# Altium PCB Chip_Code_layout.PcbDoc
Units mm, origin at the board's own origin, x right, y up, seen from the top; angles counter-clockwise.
Board outline 144.14 x 67.06 mm, 2 copper layers (Top Layer, Bottom Layer); 26 components, 21 nets, 115 pads, 10 vias.
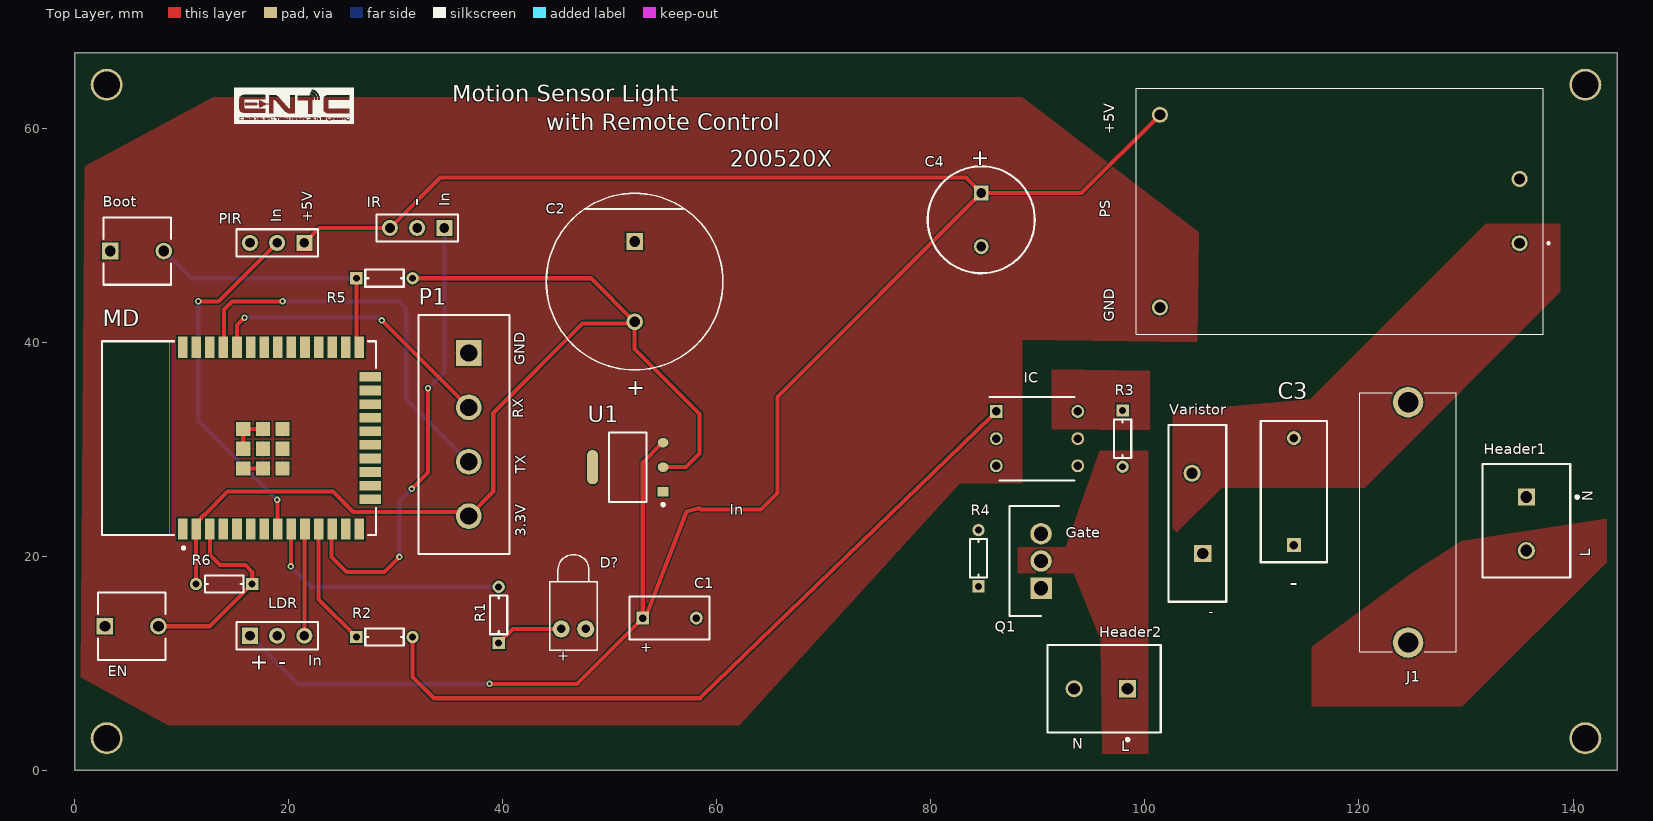
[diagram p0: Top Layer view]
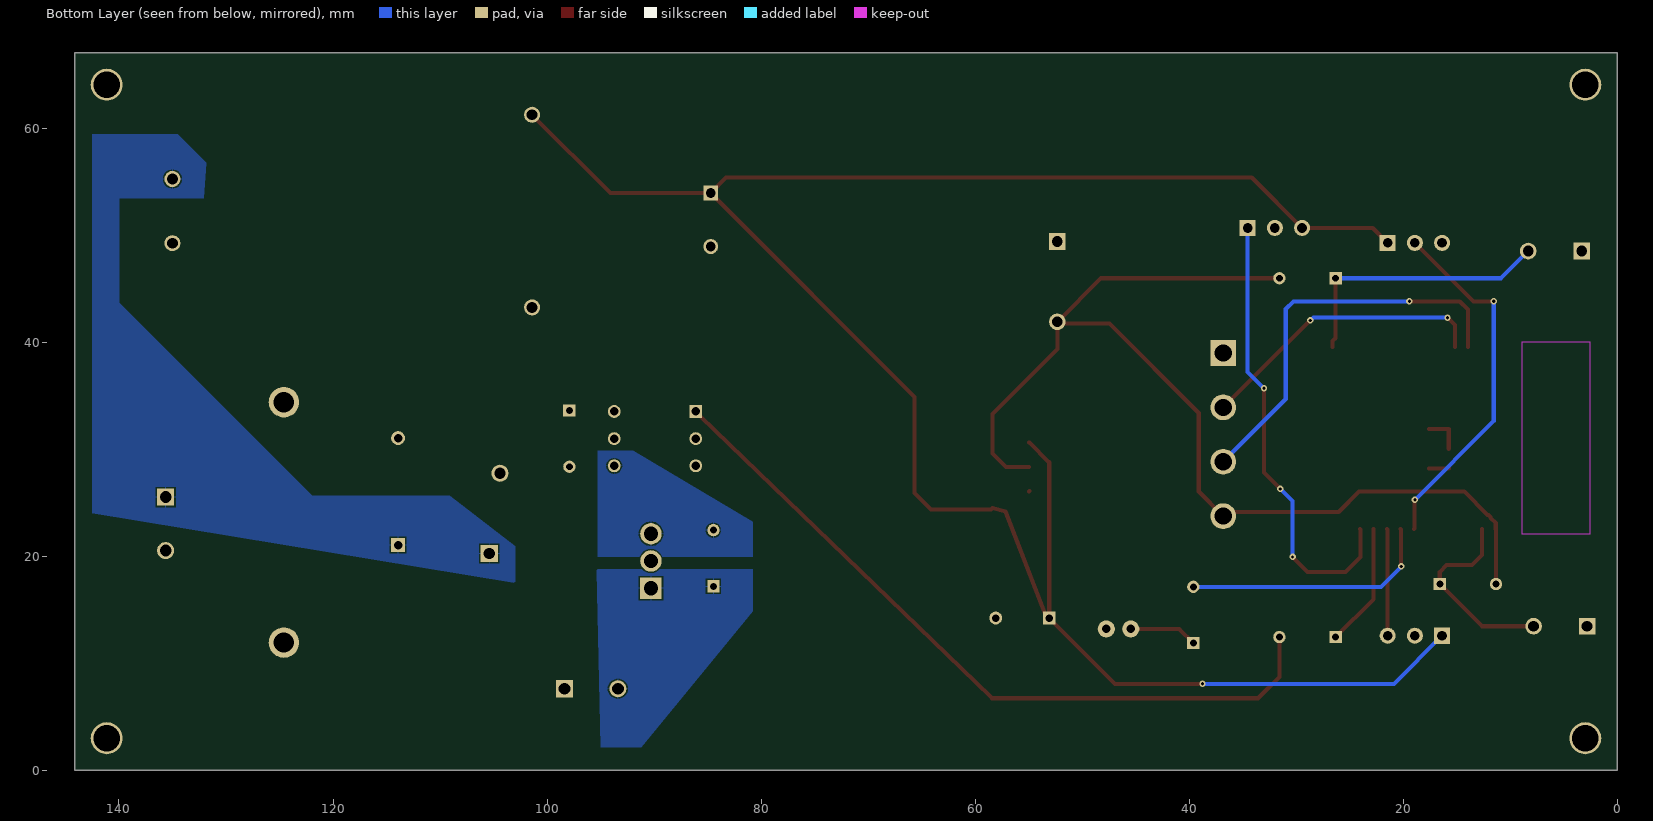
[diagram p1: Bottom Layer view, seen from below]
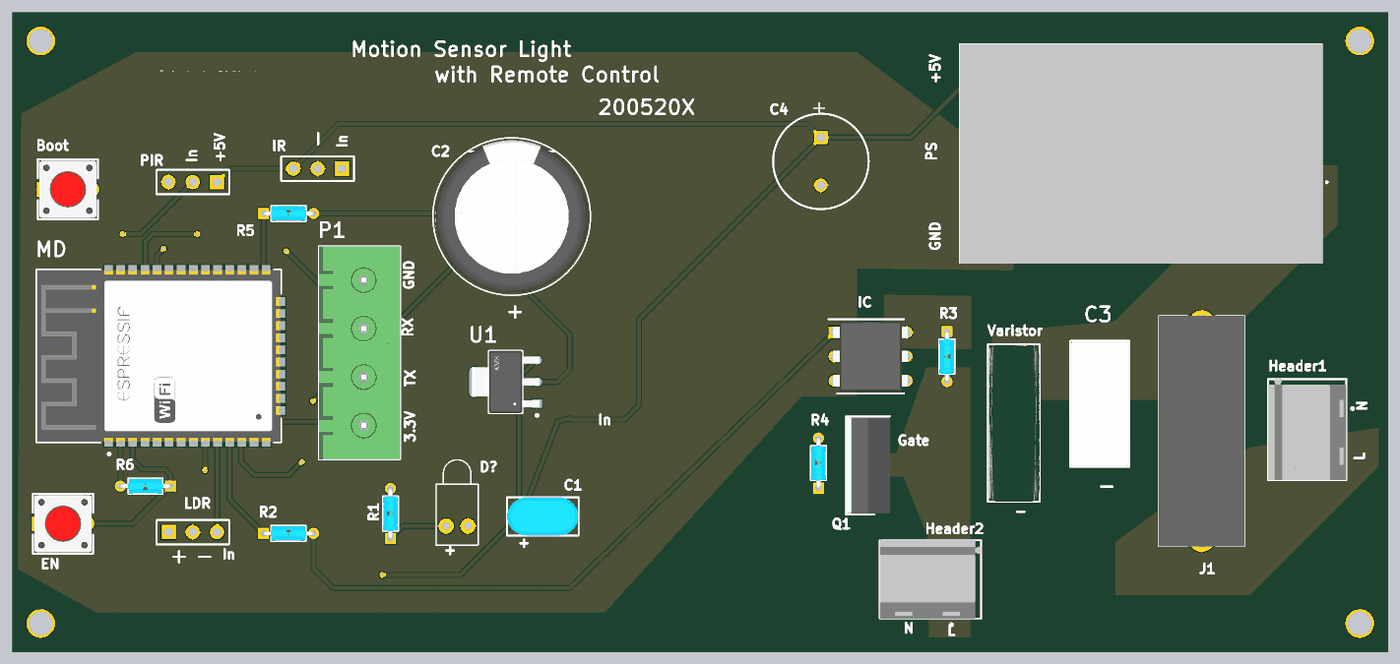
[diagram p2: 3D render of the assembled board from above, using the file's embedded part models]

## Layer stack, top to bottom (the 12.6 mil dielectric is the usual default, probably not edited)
Top Solder: solder mask 0.0102, Solder Resist, Dk 3.5
Top Layer: signal copper 0.0356
Dielectric 1: dielectric 0.32, FR-4, Dk 4.8
Bottom Layer: signal copper 0.0356
Bottom Solder: solder mask 0.0102, Solder Resist, Dk 3.5

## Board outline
0,0 144.145,0 144.145,67.056 0,67.056

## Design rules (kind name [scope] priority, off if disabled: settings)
BoardOutlineClearance [All] p1: gap=0.2 ignorepadtopadclearanceinfootprint=FALSE
Clearance [All] p1: gap=0.127 ignorepadtopadclearanceinfootprint=FALSE except(0.25: Arc-Hole Track-Hole SMDPad-Hole THPad-Hole Via-Hole Fill-Hole Poly-Hole Region-Hole Text-Hole)
ComponentClearance [All] p1: gap=0.127 collisioncheckmode=3 verticalgap=0.127 showdistances=TRUE
DiffPairsRouting [All] p1: maxlimit=0.254 minlimit=0.127 mostfreqgap=0.127 toplayer_minwidth=0.127 toplayer_maxwidth=25.4 toplayer_prefwidth=0.127 bottomlayer_minwidth=0.127 bottomlayer_maxwidth=25.4 bottomlayer_prefwidth=0.127 maxuncoupledlength=12.7
Height [All] p1: minheight=0 maxheight=1816.048 prefheight=12.7
HoleSize [All] p1: absolutevalues=TRUE maxlimit=6.3 minlimit=0.3 maxpercent=80.000 minpercent=20.000
HoleToHoleClearance [All] p1: gap=0.25 allowstackedmicrovias=FALSE
MinimumAnnularRing [All] p1: minimumring=0.076
MinimumSolderMaskSliver [All] p1: minsoldermaskwidth=0
PlaneClearance [All] p1: clearance=0.127
PlaneConnect PlaneConnectPowerPads [InPadClass('PowerPads')] p1: planeconnectstyle=Direct reliefexpansion=0.508 reliefentries=4 reliefconductorwidth=0.254 reliefairgap=0.254
PlaneConnect [All] p2: pad.planeconnectstyle=Relief pad.reliefexpansion=0.3 pad.reliefentries=4 pad.reliefconductorwidth=0.127 pad.reliefairgap=0.127 via.planeconnectstyle=Direct via.reliefexpansion=0.3 via.reliefentries=4 via.reliefconductorwidth=0.127 via.reliefairgap=0.127
PolygonConnect PolygonConnectPowerPads [All vs (InPadClass('PowerPads'))] p1: connectstyle=Direct reliefconductorwidth=0.254 reliefentries=4 polygonreliefangle="90 Angle" airgapwidth=0.254
PolygonConnect [All] p2: thpad.connectstyle=Relief thpad.reliefconductorwidth=0.127 thpad.reliefentries=4 thpad.polygonreliefangle="90 Angle" thpad.airgapwidth=0.127 smdpad.connectstyle=Relief smdpad.reliefconductorwidth=0.127 smdpad.reliefentries=4 smdpad.polygonreliefangle="90 Angle" smdpad.airgapwidth=0.127 via.connectstyle=Direct via.reliefconductorwidth=0.127 via.reliefentries=4 via.polygonreliefangle="90 Angle" via.airgapwidth=0.127
RoomDefinition Code_schematic [InComponentClass('Code_schematic')] p1: confinementstyle=ConfineIn formatcopy=TRUE lockcomponents=FALSE outline 0,0 144.145,0 144.145,67.183 0,67.183
RoutingVias [All] p1: holewidth=0.3 width=0.6 viastyle="Through Hole" minholewidth=0.3 minwidth=0.6 maxholewidth=0.6 maxwidth=6.6
SilkToSilkClearance [All] p1: silktosilkclearance=0
SilkToSolderMaskClearance [IsPad] p1: minsilkscreentomaskgap=0.127 clearancetoexposedcopper=TRUE
SolderMaskExpansion [All] p1: expansion=0.075 istentingtop=FALSE
Width [All] p1: maxlimit=25.4 minlimit=0.127 preferedwidth=1 minimp=50.000000 maximp=50.000000 favimp=50.000000
20 further rules are at their usual default settings.

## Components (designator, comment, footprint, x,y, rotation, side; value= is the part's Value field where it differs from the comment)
Boot "EVQ-21505R" FP-EVQ-21505R-MFG 5.842,48.514 r0 top
C1 "RDER72E474K4M1H03A" FP-RDE4K1-MFG 55.586,14.224 r0 top
C2 "ECA-2GM330" FP-ECA-2GM330-MFG 52.324,45.653 r270 top
C3 "R46KF3100CKM1M" FP-R46KF3100CKM1M-MFG 113.919,26.035 r90 top value=0.1uF
C4 "ECA-1HM221" CAPPR65-500-1250X1000X1350 84.709,51.435 r270 top value=220µF
D? "LED1" LED-1 46.609,13.208 r90 top
EN "EVQ-21505R" FP-EVQ-21505R-MFG 5.334,13.462 r0 top
Header1 "282836-2" TECO-282836-2_V 135.636,23.027 r270 top
Header2 "282836-2" TECO-282836-2_V 95.885,7.62 r180 top
IC "MOC3021" DIP762W60P254L730H450Q6N 89.916,30.988 r0 top
IR "Header 3" HDR1X3 34.544,50.673 r180 top
J1 "FH-320-NV" FH320NV 124.587,34.398 r270 top
LDR "Header 3" HDR1X3 16.383,12.573 r0 top
MD "ESP32-WROOM-32D" FP-ESP32-WROOM-32D-MFG 15.356,31.042 r90 top
P1 "691311500104" 691311500104 36.38,31.369 r270 top
PIR "Header 3" HDR1X3 21.463,49.276 r180 top
PS "HLK-5M05" HLK5M05 135.001,49.245 r180 top
Q1 "BT136X-600E_DG,127" TO254P460X1000X1930-3P 90.297,17.018 r90 top
R1 "MBA02040C2200FC100" FP-MBA0204-MFG 39.624,14.518 r90 top value=220Ω
R2 "MBA02040C2200FC100" FP-MBA0204-MFG 28.956,12.446 r0 top value=220Ω
R3 "56 ohm" FP-MBA0204-MFG 97.917,30.988 r270 top value=56Ω
R4 "100 ohm" FP-MBA0204-MFG 84.455,19.812 r90 top value=100Ω
R5 "10k ohm" FP-MBA0204-MFG 28.956,45.974 r0 top value=10kΩ
R6 "10k ohm" FP-MBA0204-MFG 13.97,17.399 r180 top value=10kΩ
U1 "AMS1117-3.3" FP-AMS1117-IPC_C 51.689,28.321 r180 top
Varistor "MOV-14D471K" FP-MOV-14D471K-MFG 104.902,24.003 r90 top value=516pF

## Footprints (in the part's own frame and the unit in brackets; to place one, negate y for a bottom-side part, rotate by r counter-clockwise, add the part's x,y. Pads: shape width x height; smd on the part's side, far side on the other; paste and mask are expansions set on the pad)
691311500104 [mm] "5,08mm - PCB Headers - Vertical - Closed ends -04p"
  rect 2.4x2.4 hole 1.6: 1(-7.62,0.45)
  round 2.4 hole 1.6: 2(-2.54,0.45) 3(2.54,0.45) 4(7.62,0.45)
  silkscreen extent -11.16,-4.25 11.16,4.25, body extent -11.16,-4.25 11.16,4.25, height 12.05
CAPPR65-500-1250X1000X1350 [mm] "THD, 2-Leads, Dia 10mm, Body Length 12.5mm"
  rect 1.4x1.4 hole 0.9: 1(-2.5,0)
  round 1.4 hole 0.9: 2(2.5,0)
  silkscreen extent -5,-5 5,5, body extent -5,-5 4.95,5, height 13.5
DIP762W60P254L730H450Q6N [mm]
  rect 1.2x1.2 hole 0.8: 1(-3.81,2.54)
  round 1.2 hole 0.8: 2(-3.81,0) 3(-3.81,-2.54) 4(3.81,-2.54) 5(3.81,0) 6(3.81,2.54)
  silkscreen extent -4.41,-3.9 3.5,3.9, body extent -3.96,-3.65 3.96,3.65, height 4.5
FH320NV [mm]
  round 2.85 hole 1.9: 1(0,0) 2(22.46,0)
  silkscreen extent -0.87,-4.5 23.33,4.5, body extent -0.87,-4.5 23.33,4.5, height 12.1
FP-AMS1117-IPC_C [mm]
  rect 1.004x0.872 smd paste+0 mask+0: 1(-3.295,2.29)
  rrect100% 1.004x0.872 smd paste+0 mask+0: 2(-3.295,0) 3(-3.295,-2.29)
  rrect87% 1.004x3.182 smd paste+0 mask+0: 4(3.295,0)
  silkscreen extent -3.42,-3.25 1.75,3.62, body extent -3.9,-3.35 3.9,3.35, height 0.25
FP-ECA-2GM330-MFG [mm]
  rect 1.55x1.55 hole 1 paste-1000 mask+0: 1(-3.75,0)
  round 1.55 hole 1 paste-1000 mask+0: 2(3.75,0)
  silkscreen extent -8.25,-8.25 8.25,8.25, body extent -8.35,-8.35 8.35,8.35, height 0.25
FP-ESP32-WROOM-32D-MFG [mm]
  rect 2x0.9 smd paste+0 mask+0: 1(-8.5,5.26) 2(-8.5,3.99) 3(-8.5,2.72) 4(-8.5,1.45) 5(-8.5,0.18) 6(-8.5,-1.09) 7(-8.5,-2.36) 8(-8.5,-3.63) 9(-8.5,-4.9) 10(-8.5,-6.17) 11(-8.5,-7.44) 12(-8.5,-8.71) 13(-8.5,-9.98) 14(-8.5,-11.25) 25(8.5,-11.25) 26(8.5,-9.98) 27(8.5,-8.71) 28(8.5,-7.44) 29(8.5,-6.17) 30(8.5,-4.9) 31(8.5,-3.63) 32(8.5,-2.36) 33(8.5,-1.09) 34(8.5,0.18) 35(8.5,1.45) 36(8.5,2.72) 37(8.5,3.99) 38(8.5,5.26)
  rect 0.9x2 smd paste+0 mask+0: 15(-5.715,-12.25) 16(-4.445,-12.25) 17(-3.175,-12.25) 18(-1.905,-12.25) 19(-0.635,-12.25) 20(0.635,-12.25) 21(1.905,-12.25) 22(3.175,-12.25) 23(4.445,-12.25) 24(5.715,-12.25)
  rect 1.33x1.33 smd paste+0 mask+0: 39(-2.835,-2.24) 39(-2.835,-0.405) 39(-2.835,-4.075) 39(-1,-0.405) 39(-1,-4.075) 39(-1,-2.24) 39(0.835,-0.405) 39(0.835,-4.075) 39(0.835,-2.24)
  Keep-Out Layer region: -9,6.45 9,6.45 9,12.75 -9,12.75
  Keep-Out Layer region: -9,6.45 9,6.45 9,12.75 -9,12.75
  silkscreen extent -10.4,-12.8 9.05,12.8, body extent -9.6,-13.35 9.6,12.9, height 0.25
FP-EVQ-21505R-MFG [mm]
  rect 1.55x1.55 hole 1 paste-1000 mask+0: A(-2.5,0)
  round 1.55 hole 1 paste-1000 mask+0: B(2.5,0)
  silkscreen extent -3.15,-3.15 3.15,3.15, body extent -3.37,-3.25 3.37,3.25, height 0.25
FP-MBA0204-MFG [mm]
  rect 1.15x1.15 hole 0.65 paste-1000 mask+0: 1(-2.627,0)
  round 1.15 hole 0.65 paste-1000 mask+0: 2(2.627,0)
  silkscreen extent -1.8,-0.8 1.8,0.8, body extent -3.17,-0.9 3.17,0.9, height 0.25
FP-MOV-14D471K-MFG [mm]
  rect 1.6x1.6 hole 1.05 paste-1000 mask+0: 1(-3.75,-0.5)
  round 1.6 hole 1.05 paste-1000 mask+0: 2(3.75,0.5)
  silkscreen extent -8.25,-2.7 8.25,2.7, body extent -8.35,-2.8 8.35,2.8, height 0.25
FP-R46KF3100CKM1M-MFG [mm]
  rect 1.3x1.3 hole 0.8 paste-1000 mask+0: 1(-5,0)
  round 1.3 hole 0.8 paste-1000 mask+0: 2(5,0)
  silkscreen extent -6.6,-3.1 6.6,3.1, body extent -6.7,-3.2 6.7,3.2, height 0.25
FP-RDE4K1-MFG [mm]
  rect 1.2x1.2 hole 0.7 paste-1000 mask+0: 1(-2.5,0)
  round 1.2 hole 0.7 paste-1000 mask+0: 2(2.5,0)
  silkscreen extent -3.75,-2 3.75,2, body extent -3.85,-2.1 3.85,2.1, height 0.25
HDR1X3 [mm] "Connector; Header; 3 Position"
  rect 1.5x1.5 hole 0.9: 1(0,0)
  round 1.5 hole 0.9: 2(2.54,0) 3(5.08,0)
  silkscreen extent -1.27,-1.27 6.35,1.27
HLK5M05 [mm]
  round 1.5 hole 1: 1(0,0) 2(0,-6) 3(33.6,6) 4(33.6,-12)
  silkscreen extent -2.8,-14.5 35.8,8.5, body extent -2.23,-14.5 35.77,8.5, height 18.13
LED-1 [mm] "LED; 2 Leads"
  round 1.6 hole 0.8: 1(0,1.143) 2(0,-1.143)
  silkscreen extent -2,-2.2 6.95,2.2
TECO-282836-2_V [mm] "Female Header, Pitch 5mm, 1 x 2 Position, Height 10mm"
  rect 1.6x1.6 hole 1.1: 1(-2.5,0)
  round 1.6 hole 1.1: 2(2.5,0)
  silkscreen extent -5.6,-4.1 5,4.88, body extent -5.6,-4.1 5,4.1, height 10
TO254P460X1000X1930-3P [mm]
  rect 2.01x2.01 hole 1.34: 1(0,0)
  round 2.01 hole 1.34: 2(2.54,0) 3(5.08,0)
  silkscreen extent -2.61,-1.65 7.69,2.95, body extent -2.46,-1.65 7.54,2.95, height 18.54

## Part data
Boot EN: library part CMP-05618-000118-1, "SWITCH TACTILE SPST-NO 0.02A 15V", Actuator Color=Red, Case/Package=Radial, Contact Current Rating=20mA, Contact Resistance=50mR, Max Operating Temperature=70°C, Max Voltage Rating (DC)=15V, Min Operating Temperature=-20°C, Operating Force=1.6N, Package Quantity=1
C1: library part CMP-06035-032736-1, "Ceramic Capacitor 470nF ±10% 250V X7R Radial", Capacitance=470nF, Case/Package=Radial, Dielectric=X7R, Max Operating Temperature=125°C, Min Operating Temperature=-55°C, Package Quantity=1500, Resistor Type=Ceramic, Tolerance=10%, Voltage Rating=250V
C2: library part CMP-05427-000049-1, "CAP ALUM 33UF 20% 400V RADIAL", Capacitance=33uF, Case/Package=Radial, Max Operating Temperature=85°C, Min Operating Temperature=-25°C, Package Quantity=100, Ripple Current=275mA, Tolerance=20%, Voltage Rating=400V
C3: library part CMP-03022-000002-1, "CAP FILM 0.1UF 20% 560VDC RADIAL", Capacitance=0.1uF, Manufacturer=KEMET, Package=0, Temperature="-40°C to +110°C", Temperature Range High=+110°C, Temperature Range Low=-40°C, Tolerance=20%, Voltage Rating=560V, Voltage Rating Ac=275V
C4: library part CMP-001-00028-7, "Aluminum Electrolytic Capacitor, 220 uF, +/- 20%, 50 V, -40 to 85 degC, 2-Pin THD, RoHS, Bulk", Capacitor Type=Electrolytic, Case/Package=Radial, Manufacturer=Panasonic, Max Operating Temperature=85°C, Min Operating Temperature=-40°C, Package Description="2-Pin Radial Lead, Dia 10 mm, Body Length 12.5 mm", Package Quantity=200, Package Reference=CAPPR65-500-1250X1000X1350, Ripple Current=400mA, Tolerance=20%, Voltage Rating=50V
D?: "Typical RED GaAs LED"
Header1 Header2: library part CMP-1684-00017-1, "Female Header, Pitch 5 mm, 1 x 2 Position, Height 10 mm, Tail Length 3.5 mm, Rohs, Bulk", Color=Green, Current=13.5A, Manufacturer="TE Connectivity", Package Description="Female Header, Pitch 5 mm, 1 x 2 Position, Height 10 mm, Tail Length 3.5 mm", Package Reference=THD, Standard Package=300, Voltage=300V
IC: "Integrated Circuit", Manufacturer_Name=Lite-On, Mouser Part Number=859-MOC3021
IR LDR PIR: "Header, 3-Pin"
J1: "Connector", Manufacturer_Name="Essentra Components", Mouser Part Number=144-FH-320-NV
MD: library part CMP-194065-000003-1, "WIFI MODULE 32MBITS SPI FLASH", Manufacturer="Espressif Systems", Max Frequency=2484MHz, Max Supply Voltage=3.6V, Min Supply Voltage=3V, Nominal Supply Current=500mA, Temperature="-40°C to +85°C", Temperature Range High=+85°C, Temperature Range Low=-40°C
P1: library part CMP-1502-02148-1, "Serie 311 - 5.08mm Close Vertical PCB Header WR-TBL, 4 pin", Manufacturer="Wurth Elektronik", Operating Temperature=-40to105degC
PS: "Power Supply", Manufacturer_Name=Hi-Link
Q1: "Triac", Manufacturer_Name=NXP, Manufacturer_Part_Number=BT136X-600E/DG,127
R1 R2: library part CMP-02408-000005-1, "RES 220 OHM 0.4W 1% AXIAL", Manufacturer="Vishay BC Components", Package=MBA0204, Power Rating=0.25W, Resistance=220Ω, Temperature="-55°C to +125°C", Temperature Coefficient=50ppm/°C, Temperature Range High=+125°C, Temperature Range Low=-55°C, Tolerance=1%, Voltage Rating=200V
R3: library part CMP-02408-000005-1, "RES 56 OHM 0.4W 1% AXIAL", Manufacturer="Vishay BC Components", Manufacturer Part Number=MBA02040C2200FC100, Package=MBA0204, Power Rating=0.25W, Resistance=56Ω, Temperature="-55°C to +125°C", Temperature Coefficient=50ppm/°C, Temperature Range High=+125°C, Temperature Range Low=-55°C, Tolerance=1%, Voltage Rating=200V
R4: library part CMP-02408-000005-1, "RES 100 OHM 0.4W 1% AXIAL", Manufacturer="Vishay BC Components", Manufacturer Part Number=MBA02040C2200FC100, Package=MBA0204, Power Rating=0.25W, Resistance=100Ω, Temperature="-55°C to +125°C", Temperature Coefficient=50ppm/°C, Temperature Range High=+125°C, Temperature Range Low=-55°C, Tolerance=1%, Voltage Rating=200V
R5: library part CMP-02408-000005-1, "RES 10K OHM 0.4W 1% AXIAL", Manufacturer="Vishay BC Components", Manufacturer Part Number=MBA02040C2200FC100, Package=MBA0204, Power Rating=0.25W, Resistance=10kΩ, Temperature="-55°C to +125°C", Temperature Coefficient=50ppm/°C, Temperature Range High=+125°C, Temperature Range Low=-55°C, Tolerance=1%, Voltage Rating=200V
R6: library part CMP-02408-000005-1, "RES 10 KOHM 0.4W 1% AXIAL", Manufacturer="Vishay BC Components", Manufacturer Part Number=MBA02040C2200FC100, Package=MBA0204, Power Rating=0.25W, Resistance=10kΩ, Temperature="-55°C to +125°C", Temperature Coefficient=50ppm/°C, Temperature Range High=+125°C, Temperature Range Low=-55°C, Tolerance=1%, Voltage Rating=200V
U1: library part CMP-209535-000001-1, "LDO Voltage Regulators 1A, 3.3V", Dropout Voltage=1.1V, Manufacturer="Advanced Monolithic Systems", Max Junction Temp=+125°C, Max Power Dissipation=1.2W, Max Supply Voltage=15V, Nominal Supply Current=5mA, Output Current=1A, Output Voltage=3.3V, Package=AMS1117, Temperature="-40°C to +125°C", Temperature Range Low=-40°C
Varistor: library part CMP-07402-000007-1, "VARISTOR 470V 4.5KA DISC 14MM", Capacitance=516pF, Clamping Current=50A, Clamping Voltage=775V, Manufacturer="Bourns Inc.", Package=Radial, Temperature="-40°C to +105°C", Temperature Range High=+105°C, Temperature Range Low=-40°C, Varistor Voltage=423V, Voltage Rating Ac=300V, Voltage Rating Dc=385V, Voltage Tolerance=10%

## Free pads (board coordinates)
  round 3 hole 2.5: 8(3,64.056) 9(141.145,64.056) 10(141.145,3) 11(3,3)

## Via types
v1: diameter 0.6, hole 0.3, Top Layer to Bottom Layer, 10 vias

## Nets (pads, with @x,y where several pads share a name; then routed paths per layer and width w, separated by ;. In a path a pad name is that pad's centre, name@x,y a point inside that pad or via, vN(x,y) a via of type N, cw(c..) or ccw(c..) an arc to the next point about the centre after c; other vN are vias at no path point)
3.3V: C2.2 MD.2 P1.4 R5.2 R6.2 U1.2 | length 101.7
  Top Layer w0.381: R6.2 11.355,17.411 11.355,22.531 MD.2 11.366,23.092 11.868,23.594 11.868,23.674 12.054,23.86 12.134,23.86 14.309,26.035 24.13,26.035 26.035,24.13 36.449,24.13 P1.4 ; R5.2 48.253,45.974 C2.2 C2.2@52.324,41.749 ; P1.4@36.941,23.86 39.116,26.035 39.116,33.401 47.464,41.749 C2.2@52.324,41.749 ; U1.2 57.127,28.321 58.397,29.591 58.397,33.306 52.324,39.379 C2.2@52.324,41.749
+5: C1.1 C4.1 IR.3 LDR.1 PIR.1 PS.4 U1.3 | length 200.5
  Top Layer w0.381: PIR.1@21.59,49.149 PIR.1 22.86,50.673 IR.3 34.163,55.372 83.272,55.372 C4.1 ; v1(38.765,8.08) 46.942,8.08 C1.1 ; U1.3 54.918,30.611 53.086,28.779 C1.1 ; PS.4 94.091,53.935 C4.1 ; C1.1 53.496,14.634 57.162,24.176 58.397,24.511 58.524,24.384 64.135,24.384 65.659,25.908 65.659,34.885 C4.1
  Bottom Layer w0.381: LDR.1 20.876,8.08 v1(38.765,8.08)
EN: EN.B MD.3 R6.1 | length 18.6
  Top Layer w0.381: EN.B 12.66,13.462 R6.1 16.597,18.546 15.966,19.177 13.589,19.177 12.636,20.13 MD.3
GND: Boot.A C1.2 C2.1 C4.2 D?.2 EN.A IC.2 IR.2 LDR.2 MD.39 P1.1 PIR.3 PS.3 U1.1 | length 6.1
  Top Layer w0.254: EN.A@2.667,13.462 EN.A
  Top Layer w0.381: Boot.A@3.117,48.289 Boot.A ; MD.39@15.761,28.207 MD.39@17.596,28.207 ; MD.39@15.761,30.042 15.761,31.877 MD.39@17.596,31.877 ; U1.1@54.92,26.094 U1.1
IO0: Boot.B MD.25 R5.1 | length 25.7
  Top Layer w0.381: R5.1@26.265,45.91 R5.1 26.329,40.369 26.606,40.092 MD.25
  Bottom Layer w0.381: Boot.B 10.882,45.974 R5.1
LiveIn: Header1.2 J1.2
LiveOut: Header2.1 Q1.2 R3.2
NetC3_2: C3.2 J1.1 PS.1 Varistor.2
NetD?_1: D?.1 R1.1 | length 6.4
  Top Layer w0.381: R1.1 40.941,13.208 D?.1
NetIC_1: IC.1 R2.2 | length 69.9
  Top Layer w0.381: R2.2 31.583,8.716 33.568,6.731 58.262,6.731 58.416,6.731 58.527,6.838 85.696,33.118 IC.1
NetIC_4: IC.4 Q1.3 R4.2
NetIC_6: IC.6 R3.1
NetIR_1: IR.1 MD.12 | length 42.6
  Top Layer w0.381: MD.12 24.003,22.479 24.003,19.939 25.4,18.542 28.956,18.542 v1(30.353,19.939) ; v1(31.496,26.289) 33.02,27.813 v1(33.02,35.687)
  Bottom Layer w0.381: v1(30.353,19.939) 30.353,25.146 v1(31.496,26.289) ; v1(33.02,35.687) 34.544,37.211 IR.1
NetLDR_3: LDR.3 MD.10 | length 10
  Top Layer w0.381: LDR.3 21.495,12.605 21.495,22.511 MD.10
NetMD_8: MD.8 PIR.2 | length 34
  Top Layer w0.381: v1(11.557,43.815) 13.462,43.815 PIR.2 ; v1(18.923,25.273) 18.955,25.241 18.955,22.573 MD.8
  Bottom Layer w0.381: v1(11.557,43.815) 11.557,32.639 v1(18.923,25.273)
NetMD_9: MD.9 R1.2 | length 23.7
  Top Layer w0.381: v1(20.193,19.05) 20.225,19.082 20.225,22.511 MD.9
  Bottom Layer w0.381: v1(20.193,19.05) 22.098,17.145 R1.2
Neutral: C3.1 Header1.1 PS.2 Varistor.1
NeutralOut: Header2.2 Q1.1 R4.1
Relay: MD.11 R2.1 | length 11.6
  Top Layer w0.381: MD.11 22.796,15.979 R2.1
RX: MD.34 P1.2 | length 27.5
  Top Layer w0.381: MD.34 15.176,41.592 v1(15.875,42.291) ; v1(28.702,42.037) P1.2
  Bottom Layer w0.381: v1(15.875,42.291) 28.389,42.291 28.643,42.037 v1(28.702,42.037)
TX: MD.35 P1.3 | length 37.8
  Top Layer w0.381: MD.35@13.97,39.542 13.97,43.053 14.732,43.815 v1(19.431,43.815)
  Bottom Layer w0.381: v1(19.431,43.815) 30.257,43.815 30.988,43.084 30.988,34.671 P1.3
pads on no net: IC.3 IC.5 MD.1 MD.4 MD.5 MD.6 MD.7 MD.13 MD.14 MD.15 MD.16 MD.17 MD.18 MD.19 MD.20 MD.21 MD.22 MD.23 MD.24 MD.26 MD.27 MD.28 MD.29 MD.30 MD.31 MD.32 MD.33 MD.36 MD.37 MD.38 U1.4

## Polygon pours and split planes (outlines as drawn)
GND on Top Layer "Top Layer-GND" (solid, pour order 24): 104.902,40.005 105.029,50.292 88.519,62.865 12.954,62.865 0.938,56.444 0.573,8.713 8.763,4.191 62.103,4.191 82.677,26.797 88.519,26.797 88.519,40.226
LiveOut on Top Layer "LIVEOUT_L01_P018" (solid, pour order 18): 95.758,29.845 100.33,29.845 100.33,1.524 96.012,1.524 95.885,12.192 93.345,18.415 88.138,18.415 88.138,20.828 92.583,20.828
NetIC_6 on Top Layer "NETIC_6_L01_P017" (solid, pour order 17): 91.313,37.465 100.457,37.338 100.457,31.75 91.313,31.877
LiveIn on Top Layer "LIVEIN_L01_P008" (solid, pour order 8): 125.095,18.542 115.57,11.557 115.57,5.969 129.667,5.969 143.129,19.431 143.129,23.514 129.667,21.463
NetC3_2 on Top Layer "NETC3_2_L01_P006" (solid, pour order 6): 115.443,34.671 102.616,33.528 102.616,22.606 102.997,22.225 107.188,26.416 120.523,26.416 138.811,44.704 138.811,51.054 131.826,51.054
NeutralOut on Bottom Layer "NEUTRALOUT_L02_P020" (solid, pour order 20): 94.996,2.159 95.377,18.796 80.772,18.796 80.772,14.859 91.186,2.159
NetIC_4 on Bottom Layer "NETIC_4_L02_P019" (solid, pour order 19): 91.948,29.845 95.25,29.845 95.25,19.939 80.772,19.939 80.772,23.241
Neutral on Bottom Layer "NEUTRAL_L02_P002" (solid, pour order 2): 102.997,17.526 102.997,20.955 109.093,25.654 121.92,25.654 139.954,43.688 139.954,53.467 132.08,53.467 131.826,56.769 134.493,59.436 142.494,59.436 142.494,56.769 142.494,24.003

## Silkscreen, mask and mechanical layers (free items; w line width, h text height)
Top Overlay:
  drawing of 9 lines, arcs and shapes, not listed
  text "Motion Sensor Light" at 35.306,62.484 h1.52
  text "with Remote Control" at 44.069,59.817 h1.52
  text "+5V" at 97.155,59.436 h1 r90
  text "200520X" at 61.214,56.388 h1.52
  text "-" at 32.639,52.705 h1.52 r90
  text "In" at 35.052,52.705 h1 r90
  text "In" at 19.304,51.181 h1 r90
  text "+5V" at 22.225,51.181 h1 r90
  text "GND" at 97.155,41.91 h1 r90
  text "GND" at 42.037,37.846 h1 r90
  text "+" at 51.562,35.052 h1.52
  text "RX" at 41.91,32.893 h1 r90
  text "TX" at 42.164,27.686 h1 r90
  text "N" at 141.859,25.146 h1 r90
  text "In" at 61.214,23.876 h1
  text "3.3V" at 42.164,21.844 h1 r90
  text "Gate" at 92.583,21.717 h1
  text "L" at 141.605,19.939 h1 r90
  text "-" at 113.538,16.764 h1.52
  text "-" at 106.426,15.105 h1 r180
  text "+" at 52.832,11.009 h1
  text "+" at 45.085,10.247 h1
  text "In" at 21.844,9.779 h1
  text "+" at 16.383,9.398 h1.52
  text "-" at 19.05,9.398 h1.52
  text "N" at 93.218,2.032 h1
  text "L" at 97.79,1.778 h1
Mechanical 1:
  the board outline again, w0.2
